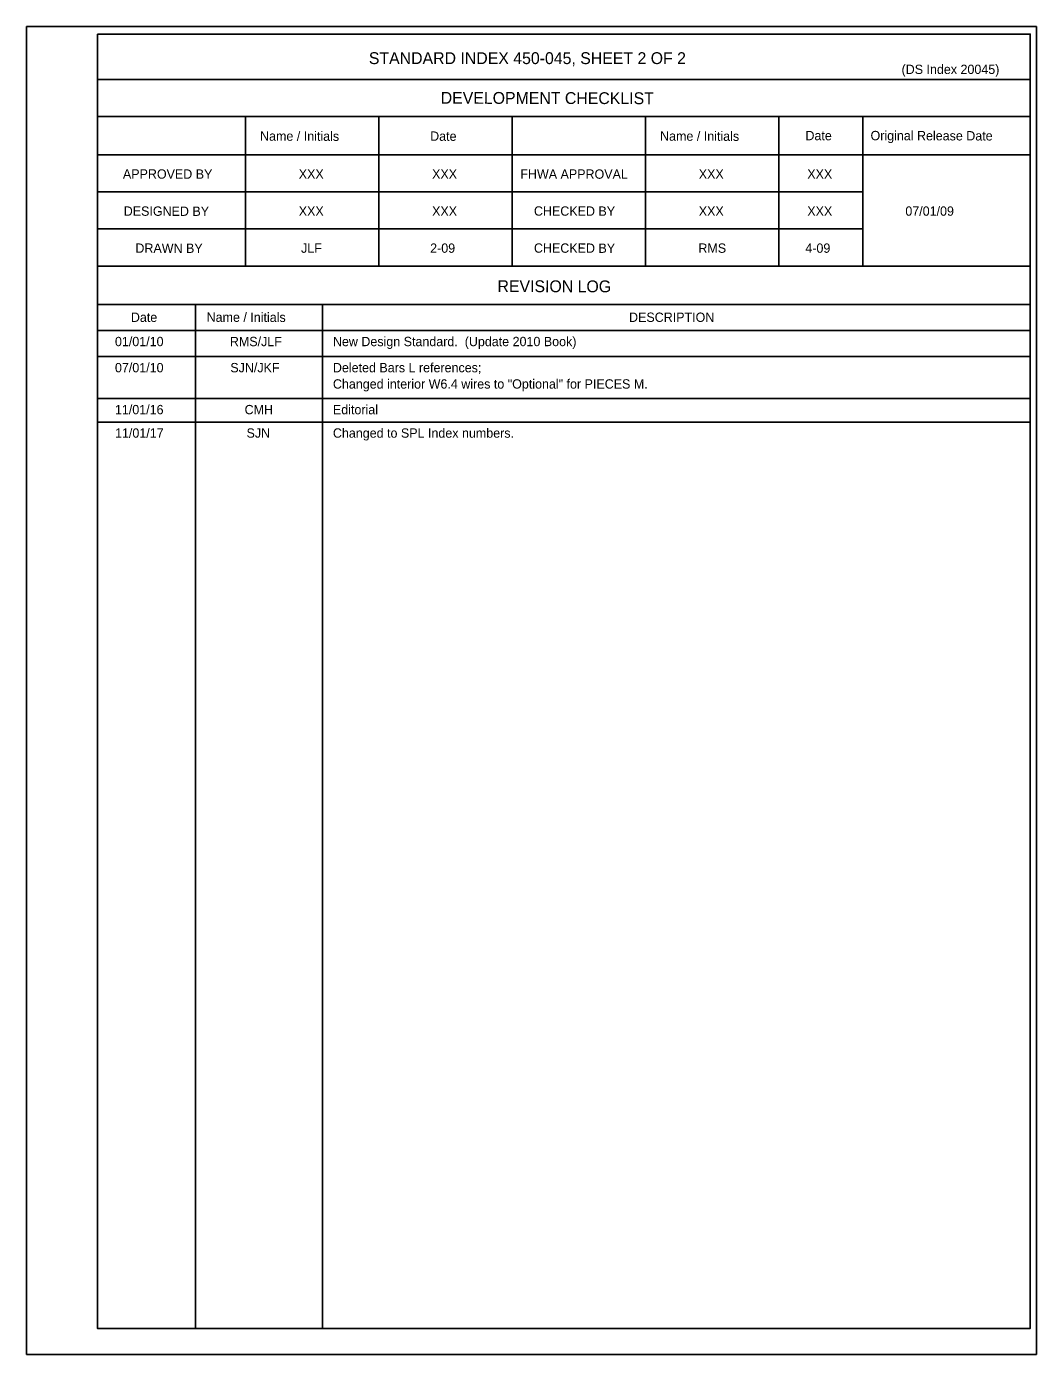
# Model space of a CAD drawing. Extents: x 4.6 to 40.7, y -1.2 to 17.4.
# Drawn here: x 29.79 to 40.7, y 2.25 to 16.59 of the extents above; entities that cross this region are included whole.
import ezdxf

# ---------------------------------------------------------------- set-up
doc = ezdxf.new("R2010")
doc.units = 0
for name, color, linetype in [('AdhocPoint_dp', 7, 'Continuous'), ('Border', 7, 'Continuous'), ('TextMisc', 7, 'Continuous')]:
    doc.layers.add(name, color=color, linetype=linetype)

msp = doc.modelspace()

# ---------------------------------------------------------------- linework, layer by layer
at = {"layer": 'AdhocPoint_dp'}
for p, q in [((30.559, 13.024), (40.633, 13.024)), ((30.559, 12.571), (40.633, 12.571)), ((30.559, 12.318), (40.633, 12.318))]:
    msp.add_line(p, q, dxfattribs=at)
at = {"layer": 'Border'}
for p, q in [((40.633, 16.015), (30.559, 16.015)), ((40.633, 15.615), (30.559, 15.615)), ((32.159, 15.615), (32.159, 14.002)), ((33.599, 15.615), (33.599, 14.002)), ((35.039, 15.615), (35.039, 14.002)), ((36.479, 15.615), (36.479, 14.002)), ((37.919, 15.615), (37.919, 14.002)), ((38.827, 15.615), (38.827, 14.002)), ((40.633, 15.202), (30.559, 15.202)), ((38.827, 14.802), (30.559, 14.802)), ((38.827, 14.402), (30.559, 14.402)), ((40.633, 14.002), (30.559, 14.002)), ((40.633, 13.588), (30.559, 13.588)), ((31.62, 13.588), (31.62, 2.534)), ((32.991, 13.588), (32.991, 2.534)), ((40.633, 13.306), (30.559, 13.306)), ((29.794, 2.254), (29.794, 2.254))]:
    msp.add_line(p, q, dxfattribs=at)
for points in [[(29.794, 16.587), (40.701, 16.587), (40.701, 2.254), (29.794, 2.254)], [(30.56, 16.506), (40.633, 16.506), (40.633, 2.534), (30.56, 2.534)]]:
    msp.add_lwpolyline(points, close=True, dxfattribs=at)

# ---------------------------------------------------------------- texts
at = {"layer": 'TextMisc'}
for s, height, p in [('STANDARD INDEX 450-045, SHEET 2 OF 2', 0.128, (33.491, 16.182)), ('(DS Index 20045)', 0.1008, (39.244, 16.075)), ('XXX', 0.1008, (32.734, 14.945)), ('XXX', 0.1008, (34.174, 14.945)), ('XXX', 0.1008, (37.054, 14.945)), ('XXX', 0.1008, (38.226, 14.945)), ('XXX', 0.1008, (32.734, 14.545)), ('XXX', 0.1008, (34.174, 14.545)), ('XXX', 0.1008, (37.054, 14.545)), ('XXX', 0.1008, (38.226, 14.545)), ('07/01/09', 0.1008, (39.285, 14.545)), ('JLF', 0.1008, (32.759, 14.145)), ('2-09', 0.1008, (34.153, 14.145)), ('RMS', 0.1008, (37.05, 14.145)), ('4-09', 0.1008, (38.205, 14.145)), ('DESCRIPTION', 0.1008, (36.301, 13.399)), ('01/01/10', 0.1008, (30.749, 13.137)), ('RMS/JLF', 0.1008, (31.99, 13.137)), ('New Design Standard.  (Update 2010 Book)', 0.1008, (33.103, 13.137)), ('07/01/10', 0.1008, (30.749, 12.855)), ('SJN/JKF', 0.1008, (31.995, 12.855)), ('Deleted Bars L references;', 0.1008, (33.103, 12.855)), ('Changed interior W6.4 wires to "Optional" for PIECES M.', 0.1008, (33.103, 12.679)), ('11/01/16', 0.1008, (30.749, 12.402)), ('CMH', 0.1008, (32.149, 12.402)), ('Editorial', 0.1008, (33.103, 12.402)), ('11/01/17', 0.1008, (30.75, 12.149)), ('SJN', 0.1008, (32.17, 12.149)), ('Changed to SPL Index numbers.', 0.1008, (33.103, 12.149))]:
    msp.add_text(s, height=height, dxfattribs=at).set_placement(p)
for s, height, p in [('DEVELOPMENT CHECKLIST', 0.128, (34.267, 15.754)), ('Name / Initials', 0.1008, (32.316, 15.355)), ('Date', 0.1008, (34.153, 15.354)), ('Name / Initials', 0.1008, (36.636, 15.355)), ('Date', 0.1008, (38.206, 15.36)), ('Original Release Date', 0.1008, (38.909, 15.36)), ('APPROVED BY', 0.1008, (30.835, 14.946)), ('FHWA APPROVAL', 0.1008, (35.127, 14.946)), ('DESIGNED BY', 0.1008, (30.844, 14.545)), ('CHECKED BY', 0.1008, (35.274, 14.546)), ('DRAWN BY', 0.1008, (30.97, 14.145)), ('CHECKED BY', 0.1008, (35.274, 14.146)), ('REVISION LOG', 0.128, (34.88, 13.721)), ('Date', 0.1008, (30.921, 13.399)), ('Name / Initials', 0.1008, (31.739, 13.4))]:
    msp.add_text(s, height=height, rotation=359.8756, dxfattribs=at).set_placement(p)

doc.saveas('drawing.dxf')
